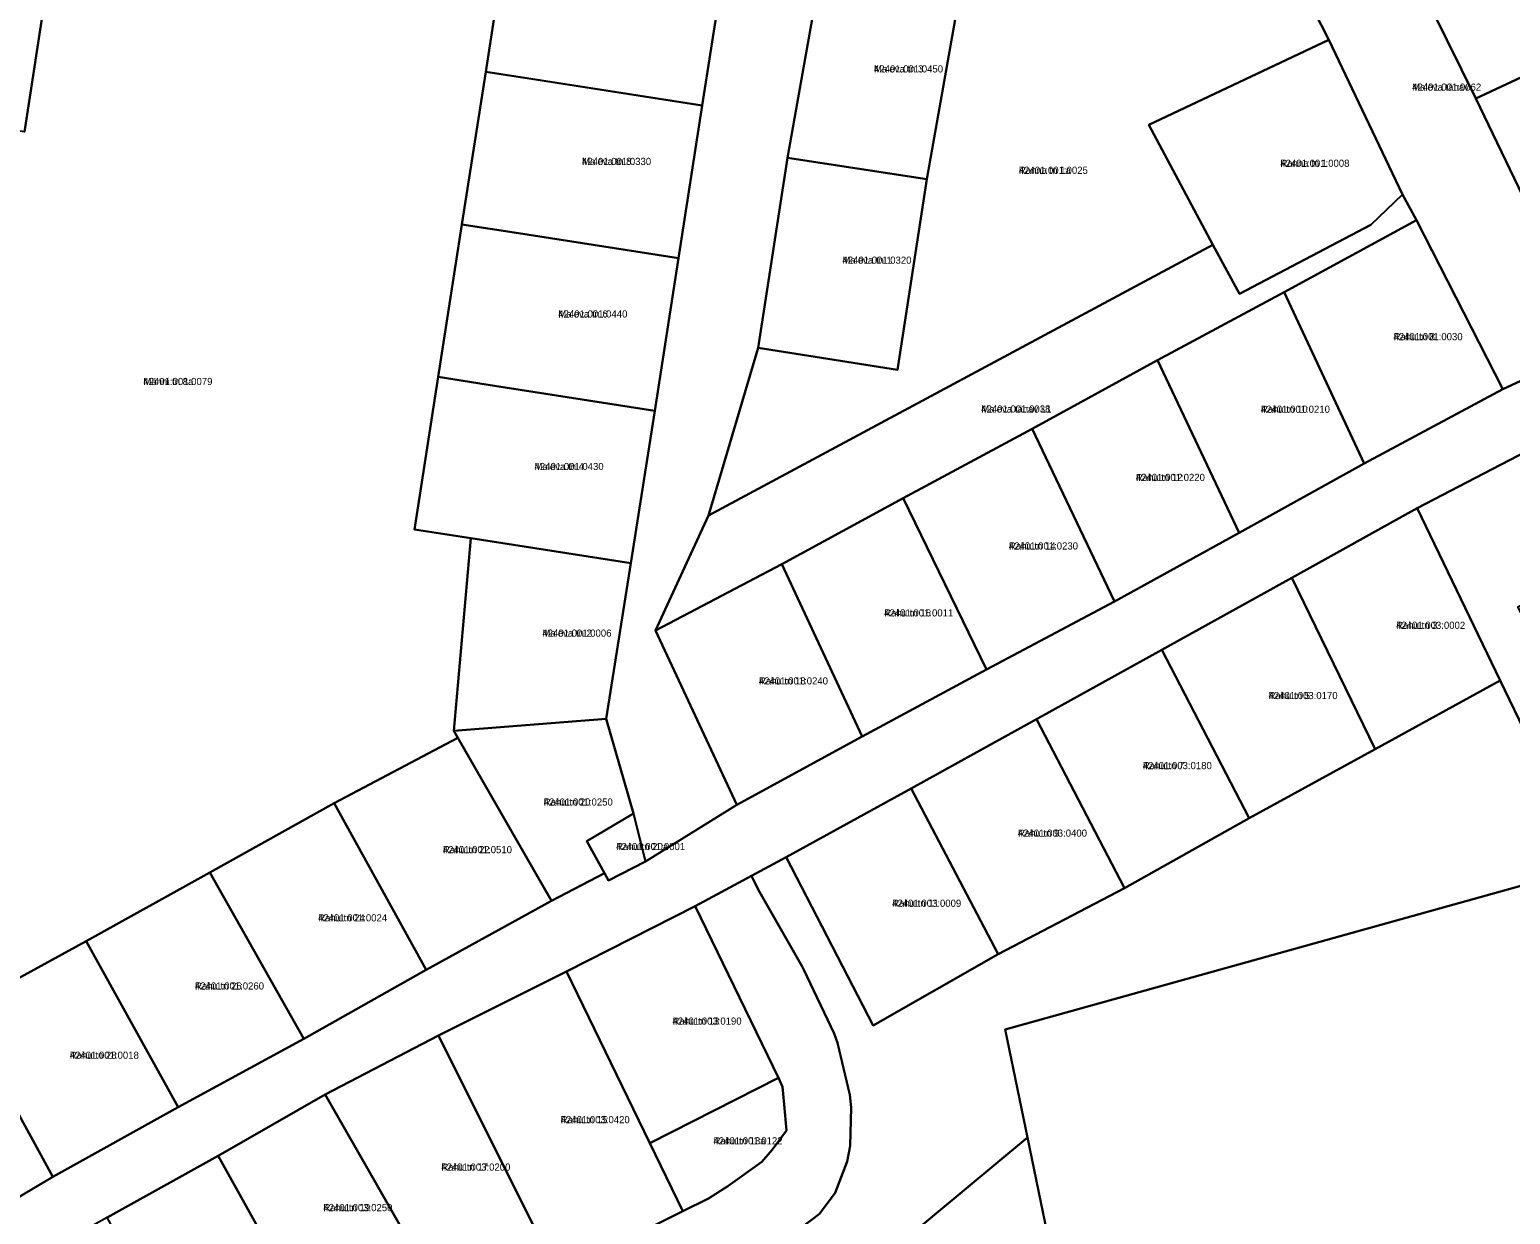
# Model space of a CAD drawing. Extents: x 595979 to 597983, y 6604231 to 6607350.
# Drawn here: x 596865.4 to 597176.2, y 6605220.6 to 6605469.2 of the extents above; entities that cross this region are included whole.
import ezdxf

# ---------------------------------------------------------------- set-up
doc = ezdxf.new("R2010")
doc.units = 0
for name, color, linetype in [('L_AADRESS', 7, 'Continuous'), ('PIIR', 7, 'Continuous'), ('TUNNUS', 7, 'Continuous')]:
    doc.layers.add(name, color=color, linetype=linetype)

msp = doc.modelspace()

# ---------------------------------------------------------------- linework, layer by layer
at = {"layer": 'PIIR'}
for points in [[(597073.01, 6605475.66), (597080.58, 6605512.09), (597103.73, 6605511.53), (597120.14, 6605502.12), (597138.08, 6605467.03), (597100.31, 6605449.17), (597113.74, 6605424.04), (597007.88, 6605367.24), (597018.25, 6605402.38), (597047.55, 6605397.79), (597053.68, 6605437.8), (597060.74, 6605477.66), (597070.69, 6605476.05)], [(597185.05, 6605500.54), (597200.03, 6605469.31), (597168.9, 6605454.75), (597153.75, 6605485.48)], [(597185.05, 6605500.54), (597200.9, 6605497.42), (597231.46, 6605450.99), (597217.98, 6605443.18), (597227.8, 6605420.87), (597194, 6605402.66), (597168.9, 6605454.75), (597200.03, 6605469.31)], [(596981.97, 6605490.48), (597011.61, 6605485.87), (597006.53, 6605453.26), (596961.09, 6605460.33), (596964.28, 6605480.86), (596976.2, 6605479.01), (596978.02, 6605491.09)], [(596868.82, 6605477.39), (596864.31, 6605447.73), (596824.76, 6605453.75), (596829.27, 6605483.41)], [(597031.63, 6605482.83), (597060.74, 6605477.66), (597053.68, 6605437.79), (597024.43, 6605442.28)], [(597153.55, 6605434.58), (597146.89, 6605428.24), (597119.3, 6605413.75), (597113.74, 6605424.04), (597100.31, 6605449.17), (597138.08, 6605467.03)], [(596972.93, 6605458.49), (597006.53, 6605453.26), (597001.55, 6605421.24), (596967.95, 6605426.47), (596956.09, 6605428.32), (596961.09, 6605460.33)], [(597053.68, 6605437.79), (597047.55, 6605397.79), (597018.25, 6605402.38), (597024.43, 6605442.28)], [(597023.28, 6605357.04), (596996.73, 6605343.09), (597007.88, 6605367.24), (597113.74, 6605424.04), (597119.3, 6605413.75), (597146.89, 6605428.24), (597153.55, 6605434.58), (597156.46, 6605429.19), (597128.69, 6605414.11), (597102.08, 6605399.79), (597075.82, 6605385.39), (597048.73, 6605370.9)], [(596967.95, 6605426.47), (597001.55, 6605421.24), (596996.56, 6605389.22), (596962.96, 6605394.46), (596951.11, 6605396.3), (596956.09, 6605428.32)], [(597174.6, 6605393.75), (597145.51, 6605378.15), (597128.69, 6605414.11), (597156.46, 6605429.19)], [(597145.51, 6605378.15), (597119.27, 6605363.58), (597102.08, 6605399.79), (597128.69, 6605414.11)], [(597102.08, 6605399.79), (597119.27, 6605363.58), (597093.1, 6605349.19), (597075.82, 6605385.39)], [(596991.57, 6605357.21), (596957.98, 6605362.44), (596946.12, 6605364.29), (596951.11, 6605396.3), (596962.96, 6605394.46), (596996.56, 6605389.22)], [(597191.72, 6605387.01), (597194.24, 6605387.32), (597206.34, 6605362.14), (597177.74, 6605348.02), (597188.94, 6605324.73), (597217.87, 6605338.8), (597226.8, 6605320.8), (597188.79, 6605302.16), (597179.96, 6605320.31), (597174.03, 6605332.6), (597156.63, 6605368.74)], [(597093.1, 6605349.19), (597066.19, 6605334.9), (597048.73, 6605370.9), (597075.82, 6605385.39)], [(597040.14, 6605320.88), (597023.28, 6605357.04), (597048.73, 6605370.9), (597066.19, 6605334.9)], [(597156.63, 6605368.74), (597174.03, 6605332.6), (597147.8, 6605318.21), (597130.33, 6605354.15)], [(596991.57, 6605357.21), (596986.37, 6605324.56), (596954.41, 6605322.03), (596957.98, 6605362.44)], [(596996.73, 6605343.09), (597023.28, 6605357.04), (597040.14, 6605320.88), (597013.8, 6605306.51)], [(597147.8, 6605318.21), (597121.32, 6605303.74), (597103, 6605339.04), (597130.33, 6605354.15)], [(597076.68, 6605324.49), (597103, 6605339.04), (597121.32, 6605303.74), (597095.19, 6605289.02)], [(596986.37, 6605324.56), (596992.12, 6605304.72), (596982.29, 6605298.92), (596986.01, 6605292.19), (596974.91, 6605286.34), (596954.41, 6605322.03)], [(597050.42, 6605309.97), (597076.68, 6605324.49), (597095.19, 6605289.02), (597068.66, 6605275.15)], [(596955.25, 6605320.55), (596974.91, 6605286.34), (596948.6, 6605271.92), (596929.29, 6605306.9)], [(597024.14, 6605295.52), (597050.42, 6605309.97), (597068.66, 6605275.15), (597042.39, 6605260.2)], [(596903.2, 6605292.29), (596929.29, 6605306.9), (596948.6, 6605271.92), (596922.91, 6605257.44)], [(596992.12, 6605304.72), (596994.62, 6605294.61), (596986.85, 6605290.66), (596986.01, 6605292.19), (596982.29, 6605298.92)], [(597070.11, 6605259.35), (597211.99, 6605298.86), (597260.5, 6605224.72), (597285.2, 6605184.34), (597299.38, 6605162.18), (597321.75, 6605127.1), (597316.32, 6605100.66), (597302.35, 6605090.93), (597218.27, 6605028.59), (597130.93, 6604964.61), (597074.78, 6605236.74)], [(596903.2, 6605292.29), (596922.91, 6605257.44), (596896.56, 6605243.05), (596877.22, 6605277.92)], [(596995.57, 6605235.53), (596978.08, 6605271.56), (597005.04, 6605285.24), (597022.52, 6605249.25)], [(596870.21, 6605228.44), (596851, 6605263.59), (596877.22, 6605277.92), (596896.56, 6605243.05)], [(596968.96, 6605222.53), (596951.16, 6605258.14), (596978.08, 6605271.56), (596995.57, 6605235.53), (597002.49, 6605221.28), (596976.15, 6605208.15)], [(596949.09, 6605207.85), (596927.39, 6605245.75), (596951.16, 6605258.14), (596968.96, 6605222.53), (596976.15, 6605208.15), (596957.67, 6605198.54), (596954.65, 6605196.96)], [(597007.88, 6605223.9), (597002.49, 6605221.28), (596995.57, 6605235.53), (597022.52, 6605249.25), (597023.39, 6605247.35), (597023.74, 6605243.63), (597024.26, 6605238.18), (597021.24, 6605234.12), (597019.02, 6605231.63), (597011.94, 6605226.52)], [(596927.39, 6605245.75), (596949.09, 6605207.85), (596935.66, 6605201.28), (596925.33, 6605196.14), (596904.92, 6605232.87)], [(597074.78, 6605236.74), (597130.93, 6604964.61), (596884.36, 6604783.54), (596826.22, 6604842.59), (596722.52, 6604944.87), (596673.89, 6604997.16), (596676.44, 6605002.97), (596651.51, 6605028.71), (596644.52, 6605036.02), (596772.01, 6605113.71), (596777.85, 6605097.85), (596847.38, 6605131.33), (596864.06, 6605103.52), (596927.46, 6605126.04), (596944.97, 6605092.68), (596998.07, 6605124.37), (597042, 6605209.45)], [(596904.92, 6605232.87), (596925.33, 6605196.14), (596901.94, 6605183.19), (596881.66, 6605219.93)]]:
    msp.add_lwpolyline(points, close=True, dxfattribs=at)
for points in [[(597153.75, 6605485.48), (597168.9, 6605454.75), (597194, 6605402.66), (597174.6, 6605393.75), (597156.46, 6605429.19), (597153.55, 6605434.58), (597138.08, 6605467.03), (597120.14, 6605502.12)], [(597031.63, 6605482.83), (597024.43, 6605442.28), (597018.25, 6605402.38), (597007.88, 6605367.24), (596996.73, 6605343.09), (597013.8, 6605306.51), (596994.62, 6605294.61), (596992.12, 6605304.72), (596986.37, 6605324.56), (596991.57, 6605357.21), (596996.56, 6605389.22), (597001.55, 6605421.24), (597006.53, 6605453.26), (597011.61, 6605485.87)], [(596964.28, 6605480.86), (596961.09, 6605460.33), (596956.09, 6605428.32), (596951.11, 6605396.3), (596946.12, 6605364.29), (596957.98, 6605362.44), (596954.41, 6605322.03), (596955.25, 6605320.55), (596929.29, 6605306.9), (596903.2, 6605292.29), (596877.22, 6605277.92), (596851, 6605263.59), (596870.21, 6605228.44), (596863.33, 6605224.33)], [(596864.31, 6605447.73), (596868.82, 6605477.39)], [(596586.98, 6605071.41), (596608.69, 6605086.35), (596611.84, 6605088.12), (596732.37, 6605155.68), (596754.93, 6605167.57), (596789.19, 6605184.96), (596837.08, 6605210.13), (596863.33, 6605224.33), (596870.21, 6605228.44), (596896.56, 6605243.05), (596922.91, 6605257.44), (596948.6, 6605271.92), (596974.91, 6605286.34), (596986.01, 6605292.19), (596986.85, 6605290.66), (596994.62, 6605294.61), (597013.8, 6605306.51), (597040.14, 6605320.88), (597066.19, 6605334.9), (597093.1, 6605349.19), (597119.27, 6605363.58), (597145.51, 6605378.15), (597174.6, 6605393.75), (597194, 6605402.66)], [(597191.72, 6605387.01), (597156.63, 6605368.74), (597130.33, 6605354.15), (597103, 6605339.04), (597076.68, 6605324.49), (597050.42, 6605309.97), (597024.14, 6605295.52), (597016.87, 6605291.63), (597005.04, 6605285.24), (596978.08, 6605271.56), (596951.16, 6605258.14), (596927.39, 6605245.75), (596904.92, 6605232.87), (596881.66, 6605219.93), (596870.26, 6605213.58), (596838.64, 6605195.76), (596802.93, 6605177.68), (596776.88, 6605161.66), (596775.35, 6605164.36), (596751.28, 6605150.91), (596753, 6605147.82), (596739.75, 6605141.48), (596618.18, 6605072.86), (596613.27, 6605068.86)], [(597021.59, 6605213.4), (597031.15, 6605220.71), (597034.41, 6605225.09), (597036.94, 6605231.7), (597037.59, 6605234.97), (597037.83, 6605243.02), (597037.55, 6605245.67), (597034.91, 6605256.6), (597034.21, 6605258.56), (597027.84, 6605271.9), (597027.5, 6605272.56), (597018.25, 6605288.72), (597016.87, 6605291.63), (597024.14, 6605295.52), (597042.39, 6605260.2), (597068.66, 6605275.15), (597095.19, 6605289.02), (597121.32, 6605303.74), (597147.8, 6605318.21), (597174.03, 6605332.6), (597179.96, 6605320.31)], [(597211.99, 6605298.86), (597070.11, 6605259.35), (597074.78, 6605236.74), (597042, 6605209.45), (596998.07, 6605124.37), (596944.97, 6605092.68), (596927.46, 6605126.04), (596864.06, 6605103.52)], [(596976.15, 6605208.15), (597002.49, 6605221.28), (597007.88, 6605223.9), (597011.94, 6605226.52), (597019.02, 6605231.63), (597021.24, 6605234.12), (597024.26, 6605238.18), (597023.74, 6605243.63), (597023.39, 6605247.35), (597022.52, 6605249.25), (597005.04, 6605285.24), (597016.87, 6605291.63), (597018.25, 6605288.72), (597027.5, 6605272.56), (597027.84, 6605271.9), (597034.21, 6605258.56), (597034.91, 6605256.6), (597037.55, 6605245.67), (597037.83, 6605243.02), (597037.59, 6605234.97), (597036.94, 6605231.7), (597034.41, 6605225.09), (597031.15, 6605220.71), (597021.59, 6605213.4)]]:
    msp.add_lwpolyline(points, dxfattribs=at)

# ---------------------------------------------------------------- texts
at = {"layer": 'L_AADRESS'}
for s, p in [('Maleva tn 3', (597042.59, 6605460.19)), ('Maleva tänav', (597155.54, 6605456.37)), ('Maleva tn 8', (596981.31, 6605440.78)), ('Ranna tn 1', (597127.89, 6605440.39)), ('Ranna tn 1a', (597072.98, 6605438.92)), ('Maleva tn 1', (597035.96, 6605420.06)), ('Maleva tn 6', (596976.33, 6605408.77)), ('Rahu tn 8', (597151.64, 6605404.01)), ('Männi tn 8a', (596889.23, 6605394.6)), ('Maleva tänav L1', (597065.11, 6605388.83)), ('Rahu tn 10', (597123.79, 6605388.78)), ('Maleva tn 4', (596971.34, 6605376.76)), ('Rahu tn 12', (597097.55, 6605374.47)), ('Rahu tn 14', (597070.91, 6605360.09)), ('Rahu tn 16', (597044.73, 6605346.04)), ('Maleva tn 2', (596972.99, 6605341.8)), ('Rahu tn 3', (597152.18, 6605343.44)), ('Rahu tn 18', (597018.43, 6605331.77)), ('Rahu tn 5', (597125.4, 6605328.7)), ('Rahu tn 7', (597099, 6605314)), ('Rahu tn 20', (596973.26, 6605306.36)), ('Rahu tn 9', (597072.8, 6605299.83)), ('Rahu tn 22', (596952.1, 6605296.37)), ('Rahu tn 20a', (596988.45, 6605297.02)), ('Rahu tn 11', (597046.4, 6605285.12)), ('Rahu tn 24', (596925.9, 6605282.06)), ('Rahu tn 26', (596900.06, 6605267.76)), ('Rahu tn 13', (597000.3, 6605260.39)), ('Rahu tn 28', (596873.78, 6605253.23)), ('Rahu tn 15', (596976.82, 6605239.71)), ('Rahu tn 13a', (597008.9, 6605235.27)), ('Rahu tn 17', (596951.77, 6605229.76)), ('Rahu tn 19', (596927.01, 6605221.25))]:
    msp.add_text(s, height=1.5, dxfattribs=at).set_placement(p)
at = {"layer": 'TUNNUS'}
for s, p in [('42401:001:0450', (597042.59, 6605460.19)), ('42401:001:0062', (597155.54, 6605456.37)), ('42401:001:0330', (596981.31, 6605440.78)), ('42401:001:0008', (597127.89, 6605440.39)), ('42401:001:0025', (597072.98, 6605438.92)), ('42401:001:0320', (597035.96, 6605420.06)), ('42401:001:0440', (596976.33, 6605408.77)), ('42401:001:0030', (597151.64, 6605404.01)), ('42401:001:0079', (596889.23, 6605394.6)), ('42401:001:0038', (597065.11, 6605388.83)), ('42401:001:0210', (597123.79, 6605388.78)), ('42401:001:0430', (596971.34, 6605376.76)), ('42401:001:0220', (597097.55, 6605374.47)), ('42401:001:0230', (597070.91, 6605360.09)), ('42401:001:0011', (597044.73, 6605346.04)), ('42401:001:0006', (596972.99, 6605341.8)), ('42401:003:0002', (597152.18, 6605343.44)), ('42401:001:0240', (597018.43, 6605331.77)), ('42401:003:0170', (597125.4, 6605328.7)), ('42401:003:0180', (597099, 6605314)), ('42401:001:0250', (596973.26, 6605306.36)), ('42401:003:0400', (597072.8, 6605299.83)), ('42401:001:0510', (596952.1, 6605296.37)), ('42401:001:0001', (596988.45, 6605297.02)), ('42401:003:0009', (597046.4, 6605285.12)), ('42401:001:0024', (596925.9, 6605282.06)), ('42401:001:0260', (596900.06, 6605267.76)), ('42401:003:0190', (597000.3, 6605260.39)), ('42401:001:0018', (596873.78, 6605253.23)), ('42401:003:0420', (596976.82, 6605239.71)), ('42401:001:0122', (597008.9, 6605235.27)), ('42401:003:0200', (596951.77, 6605229.76)), ('42401:003:0250', (596927.01, 6605221.25))]:
    msp.add_text(s, height=1.5, dxfattribs=at).set_placement(p)

doc.saveas('drawing.dxf')
